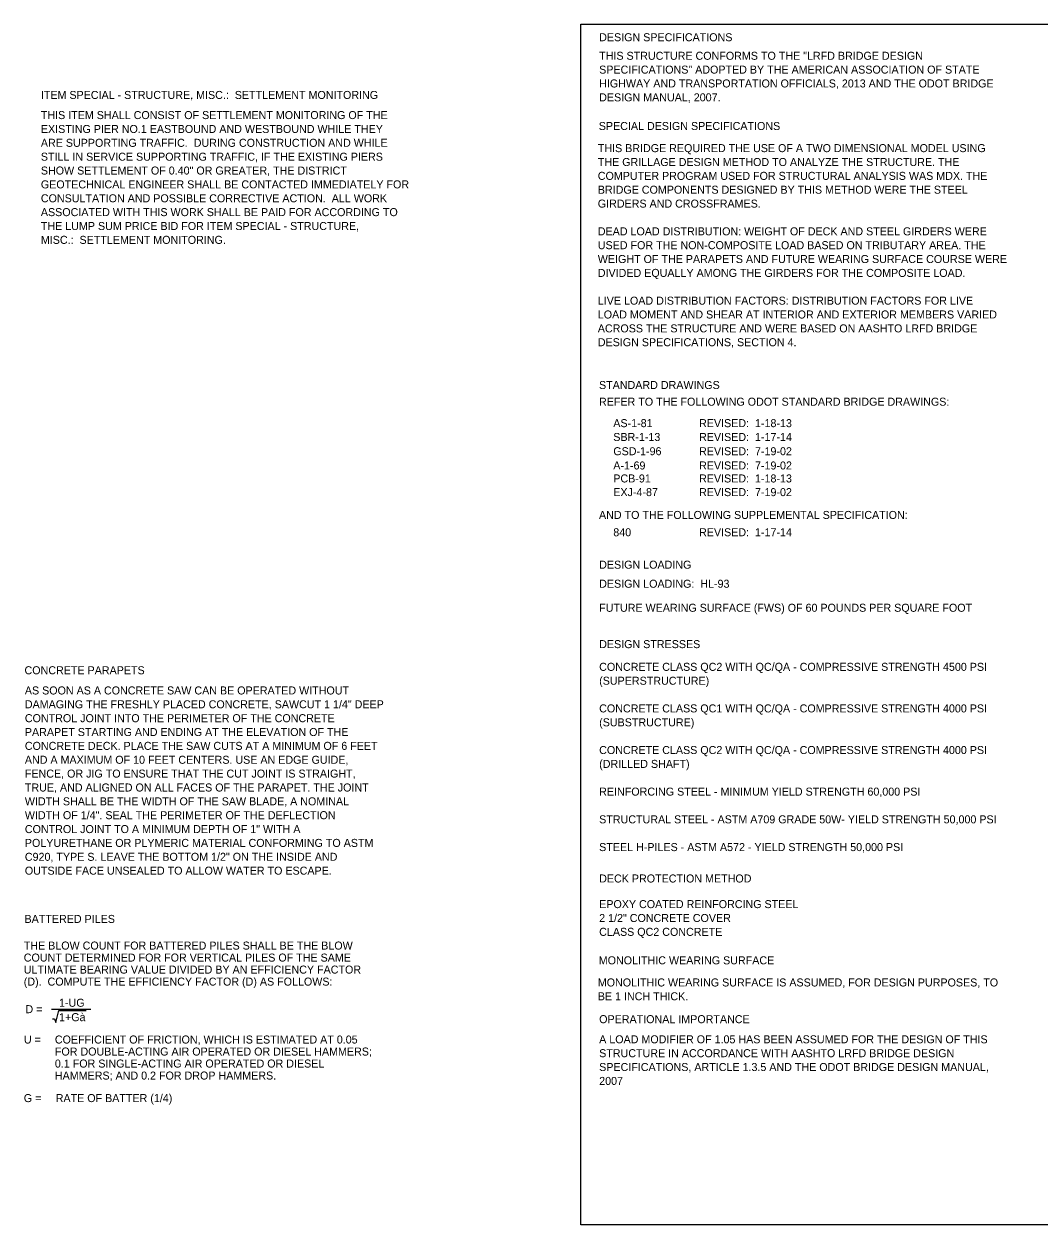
# Model space of a CAD drawing. Extents: x 1530552 to 1530730, y 675304 to 675366.
# Drawn here: x 1530689.73 to 1530707.49, y 675331.91 to 675352.91 of the extents above; entities that cross this region are included whole.
import ezdxf

# ---------------------------------------------------------------- set-up
doc = ezdxf.new("R2010")
doc.units = 0
doc.layers.add('BR_P_Gen_Text', color=7, linetype='Continuous')

msp = doc.modelspace()

# ---------------------------------------------------------------- linework, layer by layer
at = {"layer": 'BR_P_Gen_Text'}
msp.add_line((1530690.21, 675335.688), (1530690.897, 675335.688), dxfattribs=at)
msp.add_lwpolyline([(1530699.468, 675352.914), (1530729.968, 675352.914), (1530729.968, 675331.914), (1530699.468, 675331.914)], close=True, dxfattribs=at)
msp.add_lwpolyline([(1530690.229, 675335.52), (1530690.263, 675335.52), (1530690.282, 675335.455), (1530690.338, 675335.663), (1530690.815, 675335.663)], dxfattribs=at)

# ---------------------------------------------------------------- texts
for s, p in [('DESIGN SPECIFICATIONS', (1530699.786, 675352.613)), ('THIS STRUCTURE CONFORMS TO THE "LRFD BRIDGE DESIGN ', (1530699.786, 675352.289)), ('SPECIFICATIONS" ADOPTED BY THE AMERICAN ASSOCIATION OF STATE ', (1530699.786, 675352.047)), ('HIGHWAY AND TRANSPORTATION OFFICIALS, 2013 AND THE ODOT BRIDGE ', (1530699.786, 675351.805)), ('ITEM SPECIAL - STRUCTURE, MISC.:  SETTLEMENT MONITORING', (1530690.023, 675351.604)), ('DESIGN MANUAL, 2007.', (1530699.786, 675351.562)), ('THIS ITEM SHALL CONSIST OF SETTLEMENT MONITORING OF THE', (1530690.023, 675351.252)), ('SPECIAL DESIGN SPECIFICATIONS', (1530699.779, 675351.061)), ('EXISTING PIER NO.1 EASTBOUND AND WESTBOUND WHILE THEY ', (1530690.023, 675351.009)), ('ARE SUPPORTING TRAFFIC.  DURING CONSTRUCTION AND WHILE ', (1530690.023, 675350.767)), ('THIS BRIDGE REQUIRED THE USE OF A TWO DIMENSIONAL MODEL USING ', (1530699.762, 675350.674)), ('STILL IN SERVICE SUPPORTING TRAFFIC, IF THE EXISTING PIERS ', (1530690.023, 675350.524)), ('THE GRILLAGE DESIGN METHOD TO ANALYZE THE STRUCTURE. THE ', (1530699.762, 675350.431)), ('SHOW SETTLEMENT OF 0.40" OR GREATER, THE DISTRICT ', (1530690.023, 675350.282)), ('GEOTECHNICAL ENGINEER SHALL BE CONTACTED IMMEDIATELY FOR ', (1530690.023, 675350.04)), ('COMPUTER PROGRAM USED FOR STRUCTURAL ANALYSIS WAS MDX. THE ', (1530699.762, 675350.189)), ('CONSULTATION AND POSSIBLE CORRECTIVE ACTION.  ALL WORK ', (1530690.023, 675349.797)), ('BRIDGE COMPONENTS DESIGNED BY THIS METHOD WERE THE STEEL ', (1530699.762, 675349.947)), ('GIRDERS AND CROSSFRAMES.', (1530699.762, 675349.704)), ('ASSOCIATED WITH THIS WORK SHALL BE PAID FOR ACCORDING TO ', (1530690.023, 675349.555)), ('THE LUMP SUM PRICE BID FOR ITEM SPECIAL - STRUCTURE, ', (1530690.023, 675349.312)), ('DEAD LOAD DISTRIBUTION: WEIGHT OF DECK AND STEEL GIRDERS WERE ', (1530699.762, 675349.219)), ('MISC.:  SETTLEMENT MONITORING.', (1530690.023, 675349.07)), ('USED FOR THE NON-COMPOSITE LOAD BASED ON TRIBUTARY AREA. THE ', (1530699.762, 675348.977)), ('WEIGHT OF THE PARAPETS AND FUTURE WEARING SURFACE COURSE WERE ', (1530699.762, 675348.735)), ('DIVIDED EQUALLY AMONG THE GIRDERS FOR THE COMPOSITE LOAD.', (1530699.762, 675348.492)), ('LIVE LOAD DISTRIBUTION FACTORS: DISTRIBUTION FACTORS FOR LIVE ', (1530699.762, 675348.007)), ('LOAD MOMENT AND SHEAR AT INTERIOR AND EXTERIOR MEMBERS VARIED ', (1530699.762, 675347.765)), ('ACROSS THE STRUCTURE AND WERE BASED ON AASHTO LRFD BRIDGE ', (1530699.762, 675347.522)), ('DESIGN SPECIFICATIONS, SECTION 4.', (1530699.762, 675347.28)), ('STANDARD DRAWINGS ', (1530699.783, 675346.532)), ('REFER TO THE FOLLOWING ODOT STANDARD BRIDGE DRAWINGS:', (1530699.783, 675346.24)), ('AS-1-81', (1530700.033, 675345.865)), ('REVISED:  1-18-13', (1530701.533, 675345.865)), ('SBR-1-13', (1530700.033, 675345.623)), ('REVISED:  1-17-14', (1530701.533, 675345.623)), ('GSD-1-96', (1530700.033, 675345.374)), ('REVISED:  7-19-02', (1530701.533, 675345.374)), ('A-1-69', (1530700.033, 675345.125)), ('REVISED:  7-19-02', (1530701.533, 675345.125)), ('PCB-91', (1530700.033, 675344.898)), ('REVISED:  1-18-13', (1530701.533, 675344.898)), ('EXJ-4-87', (1530700.033, 675344.659)), ('REVISED:  7-19-02', (1530701.533, 675344.659)), ('AND TO THE FOLLOWING SUPPLEMENTAL SPECIFICATION:', (1530699.783, 675344.26)), ('840', (1530700.033, 675343.957)), ('REVISED:  1-17-14', (1530701.533, 675343.957)), ('DESIGN LOADING', (1530699.786, 675343.39)), ('DESIGN LOADING:  HL-93', (1530699.786, 675343.057)), ('FUTURE WEARING SURFACE (FWS) OF 60 POUNDS PER SQUARE FOOT', (1530699.786, 675342.637)), ('DESIGN STRESSES', (1530699.786, 675342.001)), ('CONCRETE CLASS QC2 WITH QC/QA - COMPRESSIVE STRENGTH 4500 PSI ', (1530699.786, 675341.604)), ('CONCRETE PARAPETS', (1530689.737, 675341.544)), ('AS SOON AS A CONCRETE SAW CAN BE OPERATED WITHOUT ', (1530689.743, 675341.191)), ('(SUPERSTRUCTURE)', (1530699.786, 675341.361)), ('DAMAGING THE FRESHLY PLACED CONCRETE, SAWCUT 1 1/4" DEEP ', (1530689.743, 675340.949)), ('CONCRETE CLASS QC1 WITH QC/QA - COMPRESSIVE STRENGTH 4000 PSI ', (1530699.786, 675340.877)), ('CONTROL JOINT INTO THE PERIMETER OF THE CONCRETE ', (1530689.743, 675340.706)), ('(SUBSTRUCTURE)', (1530699.786, 675340.634)), ('PARAPET STARTING AND ENDING AT THE ELEVATION OF THE ', (1530689.743, 675340.464)), ('CONCRETE DECK. PLACE THE SAW CUTS AT A MINIMUM OF 6 FEET ', (1530689.743, 675340.222)), ('CONCRETE CLASS QC2 WITH QC/QA - COMPRESSIVE STRENGTH 4000 PSI ', (1530699.786, 675340.149)), ('AND A MAXIMUM OF 10 FEET CENTERS. USE AN EDGE GUIDE, ', (1530689.743, 675339.979)), ('(DRILLED SHAFT)', (1530699.786, 675339.907)), ('FENCE, OR JIG TO ENSURE THAT THE CUT JOINT IS STRAIGHT, ', (1530689.743, 675339.737)), ('TRUE, AND ALIGNED ON ALL FACES OF THE PARAPET. THE JOINT ', (1530689.743, 675339.494)), ('REINFORCING STEEL - MINIMUM YIELD STRENGTH 60,000 PSI', (1530699.786, 675339.422)), ('WIDTH SHALL BE THE WIDTH OF THE SAW BLADE, A NOMINAL ', (1530689.743, 675339.252)), ('WIDTH OF 1/4". SEAL THE PERIMETER OF THE DEFLECTION ', (1530689.743, 675339.01)), ('STRUCTURAL STEEL - ASTM A709 GRADE 50W- YIELD STRENGTH 50,000 PSI', (1530699.786, 675338.937)), ('CONTROL JOINT TO A MINIMUM DEPTH OF 1" WITH A ', (1530689.743, 675338.767)), ('POLYURETHANE OR PLYMERIC MATERIAL CONFORMING TO ASTM ', (1530689.743, 675338.525)), ('STEEL H-PILES - ASTM A572 - YIELD STRENGTH 50,000 PSI', (1530699.786, 675338.452)), ('C920, TYPE S. LEAVE THE BOTTOM 1/2" ON THE INSIDE AND ', (1530689.743, 675338.282)), ('OUTSIDE FACE UNSEALED TO ALLOW WATER TO ESCAPE.', (1530689.743, 675338.04)), ('DECK PROTECTION METHOD', (1530699.786, 675337.903)), ('EPOXY COATED REINFORCING STEEL', (1530699.786, 675337.455)), ('BATTERED PILES', (1530689.737, 675337.196)), ('2 1/2" CONCRETE COVER', (1530699.786, 675337.212)), ('CLASS QC2 CONCRETE', (1530699.786, 675336.97)), ('THE BLOW COUNT FOR BATTERED PILES SHALL BE THE BLOW ', (1530689.724, 675336.73)), ('COUNT DETERMINED FOR FOR VERTICAL PILES OF THE SAME ', (1530689.724, 675336.52)), ('MONOLITHIC WEARING SURFACE', (1530699.779, 675336.472)), ('ULTIMATE BEARING VALUE DIVIDED BY AN EFFICIENCY FACTOR ', (1530689.724, 675336.31)), ('(D).  COMPUTE THE EFFICIENCY FACTOR (D) AS FOLLOWS:', (1530689.724, 675336.1)), ('MONOLITHIC WEARING SURFACE IS ASSUMED, FOR DESIGN PURPOSES, TO ', (1530699.762, 675336.085)), ('1-UG', (1530690.341, 675335.73)), ('BE 1 INCH THICK.', (1530699.762, 675335.843)), ('D =', (1530689.753, 675335.618)), ('1+Gµ', (1530690.341, 675335.478)), ('OPERATIONAL IMPORTANCE', (1530699.786, 675335.443)), ('U =', (1530689.727, 675335.087)), ('COEFFICIENT OF FRICTION, WHICH IS ESTIMATED AT 0.05 ', (1530690.268, 675335.087)), ('A LOAD MODIFIER OF 1.05 HAS BEEN ASSUMED FOR THE DESIGN OF THIS', (1530699.786, 675335.091)), ('FOR DOUBLE-ACTING AIR OPERATED OR DIESEL HAMMERS; ', (1530690.268, 675334.877)), ('0.1 FOR SINGLE-ACTING AIR OPERATED OR DIESEL ', (1530690.268, 675334.667)), ('STRUCTURE IN ACCORDANCE WITH AASHTO LRFD BRIDGE DESIGN', (1530699.786, 675334.848)), ('HAMMERS; AND 0.2 FOR DROP HAMMERS.', (1530690.268, 675334.457)), ('SPECIFICATIONS, ARTICLE 1.3.5 AND THE ODOT BRIDGE DESIGN MANUAL, ', (1530699.786, 675334.606)), ('2007', (1530699.786, 675334.363)), ('G =', (1530689.725, 675334.063)), ('RATE OF BATTER (1/4)', (1530690.283, 675334.063))]:
    msp.add_text(s, height=0.14, dxfattribs=at).set_placement(p)

doc.saveas('drawing.dxf')
